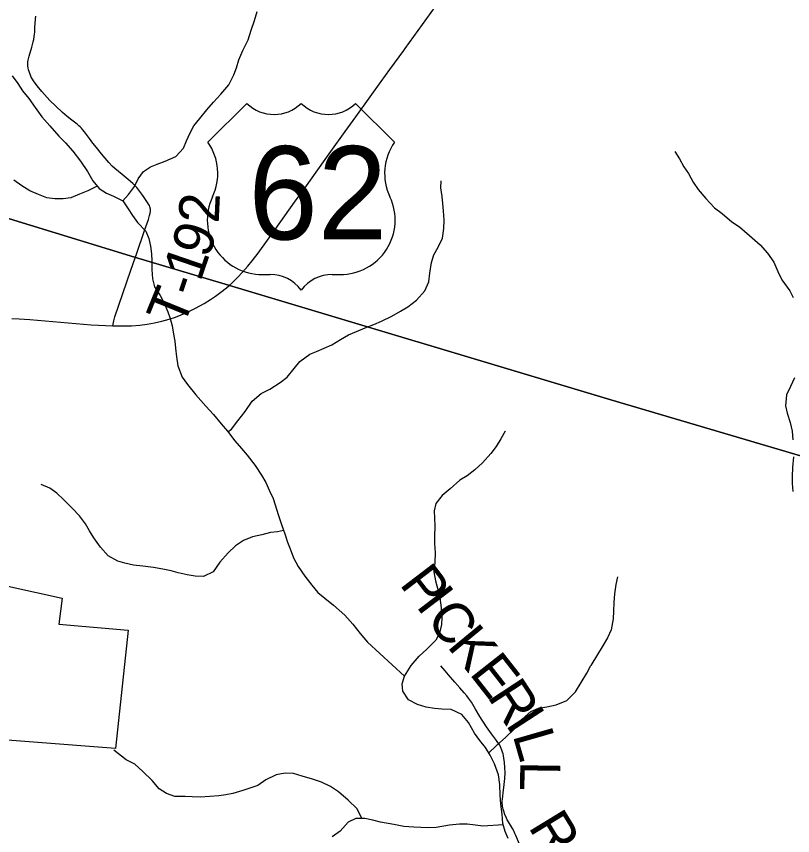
# Model space of a CAD drawing. Extents: x 1451455 to 1749751, y 218250 to 574981.
# Drawn here: x 1604125 to 1609917, y 319894 to 326004 of the extents above; entities that cross this region are included whole.
import ezdxf

# ---------------------------------------------------------------- set-up
doc = ezdxf.new("R2010")
doc.units = 0
for name, color, linetype in [('GM_X_Corporation', 7, 'Continuous'), ('GM_X_Minor_River', 7, 'Continuous'), ('GM_X_Township', 7, 'Continuous'), ('GM_X_Township_Road', 7, 'Continuous'), ('GM_X_Township_Road_Text', 7, 'Continuous'), ('GM_X_US_Location', 7, 'Continuous'), ('GM_X_US_Route', 7, 'Continuous'), ('GM_X_US_Shield', 7, 'Continuous')]:
    doc.layers.add(name, color=color, linetype=linetype)

msp = doc.modelspace()

# ---------------------------------------------------------------- linework, layer by layer
at = {"layer": 'GM_X_Corporation'}
msp.add_lwpolyline([(1600894.4, 321782.8), (1601586.6, 321717.6), (1602551.4, 321643.6), (1602650.6, 322065), (1604467.4, 321666.3), (1604443, 321472.2), (1604960, 321426.4), (1604865.9, 320543.7), (1603638.6, 320637.9), (1603496, 319066.6), (1603830.6, 319069.7), (1603743.1, 318219.8), (1602805, 317104.4), (1602731.4, 316312), (1602198.9, 316262.9), (1602217.2, 315602.4), (1602057.6, 315622.4), (1601937.9, 314443.3)], dxfattribs=at)
at = {"layer": 'GM_X_Minor_River'}
for points in [[(1604919.5, 324628.4), (1604960.8, 324675.6), (1605007.6, 324735), (1605034.4, 324792.7), (1605073.1, 324848.3), (1605125.6, 324881.6), (1605175.8, 324902.9), (1605236, 324924.1), (1605314.5, 324959), (1605371.3, 325022.3), (1605394, 325076.1), (1605418.8, 325131.8), (1605449.6, 325187.5), (1605494.3, 325243), (1605545.1, 325306.3), (1605595.9, 325363.7), (1605650.7, 325425), (1605709.6, 325494.3), (1605748.6, 325567.9), (1605767.4, 325621.7), (1605784.2, 325679.6), (1605815.1, 325749.3), (1605854.2, 325828.9), (1605877.2, 325900.7), (1605902.2, 325972.4), (1605921.1, 326040.3)], [(1604094, 325561.6), (1604137.2, 325504.9), (1604170.4, 325450.3), (1604217.5, 325391.5), (1604264.5, 325324.7), (1604315.5, 325255.9), (1604374.5, 325188.9), (1604441.4, 325111.8), (1604492.6, 325061), (1604545.7, 325000.1), (1604602.6, 324925.2), (1604655.5, 324848.3), (1604696.5, 324777.5), (1604743.6, 324720.8), (1604797.1, 324686), (1604848.7, 324663.2), (1604920.2, 324628.1), (1604959.3, 324569.4), (1604990.6, 324518.9), (1605029.8, 324468.2), (1605090.9, 324403.2), (1605114.1, 324348.8), (1605125.3, 324290.5), (1605132.5, 324234.3), (1605135.7, 324182.2), (1605134.8, 324116.1), (1605141.9, 324047.9), (1605157, 323987.5), (1605198.1, 323922.8), (1605227.2, 323864.3), (1605254.3, 323801.8), (1605271.6, 323751.5), (1605286.8, 323697.1), (1605297.9, 323634.9), (1605307.2, 323582.6), (1605312.5, 323530.5), (1605319.5, 323464.2), (1605330.6, 323398), (1605363.4, 323313.3), (1605402.6, 323258.7), (1605465.4, 323181.7), (1605538.2, 323096.5), (1605595.3, 323035.5), (1605652.3, 322966.6), (1605699.4, 322911.8), (1605756.4, 322838.9), (1605805.5, 322782.1), (1605846.8, 322731.4), (1605907.6, 322654.4), (1605954.6, 322583.6), (1605987.8, 322527), (1606014.9, 322464.5), (1606040.1, 322408), (1606080.3, 322281.2), (1606105.2, 322206.7), (1606128.3, 322144.3), (1606149.4, 322083.9), (1606168.7, 322033.5), (1606193.8, 321967), (1606228.8, 321902.4), (1606277.8, 321829.6), (1606330.8, 321762.7), (1606374, 321708), (1606427.3, 321665.1), (1606492.6, 321614.1), (1606575.4, 321538.8), (1606636.4, 321471.8), (1606689.4, 321402.9), (1606744.4, 321336), (1607021.4, 321082.6)], [(1609039.7, 324995.7), (1609072.9, 324941.1), (1609106.1, 324882.6), (1609141.3, 324832), (1609176.4, 324767.3), (1609211.6, 324712.8), (1609268.6, 324645.8), (1609333.6, 324576.8), (1609392.9, 324533.8), (1609464, 324472.7), (1609521.4, 324435.8), (1609594.5, 324370.6), (1609675.4, 324299.4), (1609730.5, 324238.5), (1609777.5, 324171.7), (1609806.5, 324101.1), (1609837.6, 324040.6), (1609896.4, 323957.6), (1609921.7, 323907.1)], [(1604728.4, 324739.1), (1604659.4, 324702), (1604595.2, 324678.8), (1604530.9, 324651.7), (1604474.8, 324642.5), (1604412.8, 324643.4), (1604353, 324652.2), (1604289.4, 324675.2), (1604225.8, 324702.2), (1604166.4, 324741.1), (1604105.1, 324784)], [(1605703.7, 322906.4), (1605729.6, 322925.4), (1605778.5, 322988.8), (1605831.4, 323058.2), (1605884.4, 323133.6), (1605951.1, 323190.7), (1606017.5, 323223.8), (1606094.1, 323272.8), (1606144.7, 323314.2), (1606197.5, 323377.5), (1606240.2, 323431), (1606314.9, 323484), (1606365.2, 323505.3), (1606421.4, 323528.6), (1606479.8, 323555.8), (1606544.3, 323594.9), (1606602.7, 323628.2), (1606739.4, 323686.3), (1606791.6, 323705.6), (1606849.9, 323730.8), (1606926.4, 323767.8), (1606990.8, 323804.9), (1607045.2, 323838.2), (1607109.9, 323887.4), (1607172.8, 323958.6), (1607201.7, 324024.3), (1607210.6, 324090.3), (1607223.7, 324168.2), (1607240.5, 324226.1), (1607273.3, 324283.7), (1607304.2, 324351.4), (1607315.2, 324423.4), (1607316.1, 324485.5), (1607313, 324553.7), (1607307.8, 324609.8), (1607302.6, 324662), (1607291.5, 324726.3), (1607294.2, 324778.3)], [(1609931.3, 323307.9), (1609900.4, 323244.2), (1609871.6, 323182.5), (1609864.4, 323098.5), (1609875.6, 323046.2), (1609898.6, 322975.8), (1609913.7, 322909.5), (1609918.8, 322845.3)], [(1607773.6, 322910.1), (1607740.8, 322852.5), (1607706.1, 322796.9), (1607665.4, 322745.4), (1607602.4, 322674.1), (1607545.8, 322622.8), (1607489.2, 322577.6), (1607434.8, 322544.3), (1607361.9, 322481.2), (1607303.3, 322430), (1607254.5, 322370.6), (1607243.7, 322316.6), (1607245, 322262.5), (1607248.1, 322202.3), (1607245, 322124.3), (1607246.3, 322072.1), (1607251.3, 322004), (1607248.3, 321931.9), (1607241.4, 321861.8), (1607252.4, 321793.5), (1607273.3, 321719.1), (1607284.6, 321668.9), (1607295.5, 321592.6), (1607300.5, 321518.4), (1607297.8, 321468.3), (1607282.9, 321404.4), (1607254.2, 321352.7), (1607187.3, 321285.6), (1607130.6, 321232.3)], [(1609923, 322719), (1609915.9, 322640.9), (1609913, 322572.9), (1609914.2, 322520.7), (1609919.4, 322460.6)], [(1606118.4, 322171.1), (1606074.6, 322159.1), (1606022.5, 322153.8), (1605956.4, 322138.7), (1605888.2, 322121.7), (1605819.9, 322094.6), (1605761.4, 322055.4), (1605706.7, 322002.1), (1605643.8, 321934.8), (1605592.8, 321861.5), (1605522.4, 321826.4), (1605458.5, 321829.3), (1605400.7, 321840.2), (1605333, 321855.2), (1605279.2, 321870), (1605217.4, 321880.9), (1605147.7, 321893.9), (1605067.9, 321903), (1605000.1, 321912), (1604934.3, 321925), (1604882.6, 321941.8), (1604811.2, 321980.9), (1604752.1, 322045.8), (1604703.1, 322114.6), (1604669.9, 322167.2), (1604640.7, 322219.7), (1604595.5, 322278.5), (1604542.4, 322337.3), (1604479.3, 322398.4), (1604428.1, 322449.2), (1604374.6, 322486), (1604311.1, 322513)], [(1608611.6, 321824.1), (1608598.8, 321766.2), (1608587.9, 321696.3), (1608583, 321632.2), (1608580.1, 321568.1), (1608577.3, 321510.1), (1608564.1, 321430.1), (1608535.3, 321370.4), (1608502.6, 321314.8), (1608411.7, 321162.3)], [(1607794.8, 319872.9), (1607771.5, 319925.2), (1607756.2, 319985.5), (1607749.1, 320053.7), (1607740, 320127.9), (1607734.9, 320196.1), (1607731.9, 320276.2), (1607722.8, 320348.4), (1607691.8, 320428.9), (1607660.6, 320495.4), (1607625.3, 320552), (1607583.9, 320604.6), (1607544.5, 320657.1), (1607499.5, 320737.9), (1607448.2, 320798.6), (1607370.6, 320833.7), (1607300.6, 320836.6), (1607244.6, 320843.4), (1607182.7, 320852.2), (1607118.8, 320871.1), (1607051.2, 320908), (1607008, 320972.7), (1607002.7, 321026.8), (1607021.4, 321082.6), (1607070.5, 321162.1), (1607130.6, 321232.3)], [(1607650.7, 320511.2), (1607705.5, 320562.9), (1607778.4, 320628), (1607843.2, 320691.2), (1607898.2, 320762.6), (1607963, 320819.8), (1608021.3, 320845.1), (1608083.5, 320854.2), (1608153.8, 320869.3), (1608232.2, 320902.3), (1608297.1, 320967.6), (1608340.1, 321037.1), (1608382.9, 321104.6), (1608411.7, 321162.3)], [(1606701.7, 320021.5), (1606668.6, 320094.1), (1606601.4, 320159), (1606528.1, 320220.1), (1606468.5, 320260.9), (1606402.9, 320293.8), (1606335.1, 320314.8), (1606257.3, 320337.8), (1606193.5, 320356.7), (1606131.5, 320359.5), (1606063.3, 320348.4), (1605986.7, 320311.4), (1605926.1, 320268.1), (1605867.8, 320246.9), (1605815.5, 320229.6), (1605741.2, 320208.5), (1605689, 320199.2), (1605634.9, 320191.9), (1605568.8, 320186.8), (1605496.7, 320181.7), (1605436.6, 320182.5), (1605384.6, 320185.2), (1605308.5, 320186.2), (1605244.8, 320209.1), (1605191.2, 320243.9), (1605137.9, 320304.6), (1605068.7, 320371.6), (1605009.3, 320426.5), (1604943.7, 320459.4), (1604852.5, 320532.7)], [(1607758.7, 319975.7), (1607605.8, 319963.5), (1607551.9, 319972.2), (1607489.9, 319979), (1607431.9, 319979.8), (1607357.7, 319972.8), (1607257.4, 319954.1), (1607201.3, 319952.8), (1607143.3, 319953.6), (1607091.3, 319958.3), (1607017.3, 319963.3), (1606941.4, 319976.3), (1606841.5, 319995.7), (1606785.6, 320008.4), (1606725.7, 320021.2), (1606657.7, 320022.1), (1606601.3, 319994.8), (1606540.4, 319927.6), (1606481.8, 319886.3)]]:
    msp.add_lwpolyline(points, dxfattribs=at)
at = {"layer": 'GM_X_Township'}
for points in [[(1615589.3, 321106.6), (1615010.3, 321279.4), (1612831.2, 321883.2), (1608561, 323144.8), (1605657, 324014), (1605007.7, 324208.4), (1603446, 324685.1), (1604039.4, 332057.3), (1604326.7, 335626.5), (1604589.6, 338933.2), (1605120, 345606.5), (1605455, 350781)], [(1593145.7, 323595.7), (1593983, 323674.9), (1599358.9, 324248.8), (1600819.8, 324404.7), (1603446, 324685.1), (1605007.7, 324208.4), (1605657, 324014), (1608561, 323144.8), (1612831.2, 321883.2), (1615010.3, 321279.4), (1615589.3, 321106.6)]]:
    msp.add_lwpolyline(points, dxfattribs=at)
at = {"layer": 'GM_X_Township_Road'}
for points in [[(1605124.6, 324570.8), (1605123.7, 324576), (1605121.4, 324584.1), (1605117.4, 324593.5), (1605111.3, 324602.8), (1605102.4, 324616.6), (1605068.7, 324667.2), (1605046.5, 324699.4), (1605023.5, 324727.1), (1604993.6, 324757.5), (1604959.4, 324788.1), (1604914.3, 324825.9), (1604858.6, 324870.7), (1604839.4, 324888.2), (1604814.9, 324914.5), (1604759.5, 324979.4), (1604722.6, 325025.5), (1604696.7, 325059.4), (1604671, 325093.4), (1604634.1, 325143.5), (1604619.4, 325161.1), (1604611.1, 325170), (1604601.3, 325180.1), (1604592.1, 325188.8), (1604579.3, 325199.7), (1604540.1, 325229.4), (1604504.1, 325257.6), (1604469.2, 325287.2), (1604418.4, 325333.5), (1604374.4, 325377.7), (1604314.9, 325443.3), (1604279.7, 325486.5), (1604253, 325523.7), (1604245.7, 325535.8), (1604236.7, 325552), (1604230.6, 325564.8), (1604224.8, 325578.8), (1604220, 325592.7), (1604216.2, 325606.6), (1604213.1, 325620), (1604211.8, 325632), (1604210.8, 325642.1), (1604210.9, 325654.4), (1604211.5, 325665.8), (1604213.1, 325676.7), (1604220, 325708.1), (1604240.9, 325775.9), (1604246.3, 325794.7), (1604251.2, 325813.3), (1604255.2, 325832.8), (1604258.8, 325854.4), (1604260.5, 325871.7), (1604261.8, 325886.2), (1604263.4, 325921.6), (1604266.7, 325983.6), (1604269.4, 326005.3)], [(1605011.5, 324204.4), (1605020.9, 324231.4), (1605081.4, 324408.3), (1605109.9, 324488.8), (1605119.5, 324519.7), (1605123.4, 324536.8), (1605125.1, 324549.1), (1605125.2, 324557.8), (1605124.9, 324568.7), (1605124.6, 324570.8)], [(1604845, 323696.1), (1604852.2, 323733.5), (1604859.3, 323762.5), (1604978.9, 324110.5), (1605011.5, 324204.4)], [(1607879.2, 319829.3), (1607852, 319896.1), (1607845.6, 319911.2), (1607837.5, 319928.9), (1607828, 319946.3), (1607796.9, 319996.4), (1607788.6, 320011.3), (1607781.5, 320025.2), (1607770.1, 320052.4), (1607761.8, 320077.3), (1607757.7, 320090.4), (1607755, 320102.6), (1607753.2, 320112.8), (1607751.8, 320122), (1607751.2, 320133.7), (1607750.8, 320144.9), (1607750.9, 320154.5), (1607751.6, 320164.6), (1607757.5, 320213.4), (1607765.8, 320275.2), (1607769.8, 320320.9), (1607771.4, 320363.6), (1607770.7, 320402.9), (1607767.8, 320438.9), (1607763.3, 320471.3), (1607760.3, 320488.2), (1607756.6, 320503.5), (1607752.7, 320517.7), (1607748.1, 320531.7), (1607743.2, 320544.1), (1607737.8, 320557), (1607732, 320568.8), (1607723.7, 320581.9), (1607713.2, 320596.8), (1607700.7, 320614.2), (1607671.4, 320654.2), (1607633.7, 320706.5), (1607614.7, 320733.2), (1607600.1, 320755), (1607582.8, 320782.8), (1607552, 320836.8), (1607520.1, 320890.1), (1607499.8, 320919.8), (1607485.8, 320937.9), (1607466.7, 320960.3), (1607433.4, 320996), (1607396.5, 321037.6), (1607348.6, 321093.9), (1607324.6, 321122.8), (1607292.7, 321160.3)]]:
    msp.add_lwpolyline(points, dxfattribs=at)
at = {"layer": 'GM_X_US_Route'}
for points in [[(1607015.7, 325750.9), (1607026.1, 325765.2), (1607252.5, 326079.2)], [(1604090.9, 323751.5), (1604146.8, 323748.9), (1604225.3, 323742.8), (1604398.4, 323727.7), (1604682.7, 323704.6), (1604845, 323696.1), (1604927.3, 323695.3), (1604983.2, 323697.5), (1605045.5, 323702.5), (1605101.1, 323709.6), (1605156.3, 323719.1), (1605210.9, 323731.3), (1605265, 323746.1), (1605312, 323761.3), (1605355.2, 323777.4), (1605406.6, 323799.7), (1605462.6, 323827.5), (1605526, 323862.4), (1605573.7, 323891.6), (1605611.9, 323917.3), (1605651.7, 323946.6), (1605692.7, 323979.6), (1605712.9, 323997.5), (1605734.6, 324016.8), (1605774.8, 324055.7), (1605813.4, 324096.2), (1605852.4, 324140.7), (1605885.5, 324181.6), (1605929.1, 324239.2), (1606055.4, 324414.9), (1606199.8, 324618), (1606277, 324724), (1606471.6, 324996.2), (1606579.3, 325145), (1606658.2, 325254), (1606765.6, 325403.1), (1606846.8, 325518.3), (1606912.9, 325608.1), (1607015.7, 325750.9)]]:
    msp.add_lwpolyline(points, dxfattribs=at)
at = {"layer": 'GM_X_US_Shield'}
for p, q in [((1605844.5, 325355.6), (1605554.5, 325065.5)), ((1606946.7, 325065.5), (1606656.6, 325355.6)), ((1605960.6, 324079.4), (1606018.6, 324079.4)), ((1606482.6, 324079.4), (1606540.6, 324079.4))]:
    msp.add_line(p, q, dxfattribs=at)
for centre, radius, start, end in [((1606047.6, 325562.7), 290, 225.573, 314.427), ((1606453.6, 325562.7), 290, 225.573, 314.427), ((1605221.9, 324832.6), 406.1, 334.54712, 35.00093), ((1607279.3, 324832.6), 406.1, 144.99907, 205.45288), ((1605956, 324485.4), 406.1, 154.83192, 270.63826), ((1606545.2, 324485.4), 406.1, 269.36174, 25.16808), ((1606018.6, 323789.4), 290, 36.8699, 90), ((1606482.6, 323789.4), 290, 90, 143.1301)]:
    msp.add_arc(centre, radius, start, end, dxfattribs=at)

# ---------------------------------------------------------------- texts
at = {"layer": 'GM_X_Township_Road_Text'}
for s, rotation, p in [('2', 87.27626, (1605634.4, 324458.1)), ('9', 71.06888, (1605557.1, 324192.7)), ('1', 71.08534, (1605497.2, 324017.9)), ('-', 71.40337, (1605458, 323901.5)), ('T', 67.82534, (1605366.2, 323674.6)), ('P', 307.35741, (1606978, 321769.7)), ('I', 307.35777, (1607100.8, 321608.9)), ('C', 307.37423, (1607175.7, 321510.8)), ('K', 309.51658, (1607332.9, 321305.4)), ('E', 308.15314, (1607499.6, 321103.3)), ('R', 303.36748, (1607634.4, 320932.2)), ('I', 302.94746, (1607769.6, 320726.9)), ('L', 286.03076, (1607826.9, 320644.7)), ('L', 269.09568, (1607885.8, 320452.2)), ('R', 301.44112, (1607940.7, 319959.9))]:
    msp.add_text(s, height=300, rotation=rotation, dxfattribs=at).set_placement(p)
at = {"layer": 'GM_X_US_Location'}
for s in ['/', '0']:
    msp.add_text(s, height=1, dxfattribs=at).set_placement((1606250.3, 324683))
msp.add_text('62', height=1, rotation=0.00001, dxfattribs=at).set_placement((1606043.8, 324476))
at = {"layer": 'GM_X_US_Shield'}
msp.add_text('62', height=696.1, dxfattribs=at).set_placement((1605856.5, 324340.4))

doc.saveas('drawing.dxf')
